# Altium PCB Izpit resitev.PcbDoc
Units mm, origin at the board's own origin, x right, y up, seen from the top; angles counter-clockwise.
Board outline 115 x 60 mm, 2 copper layers (Top Layer, Bottom Layer); 20 components, 19 nets, 110 pads, 8 vias.
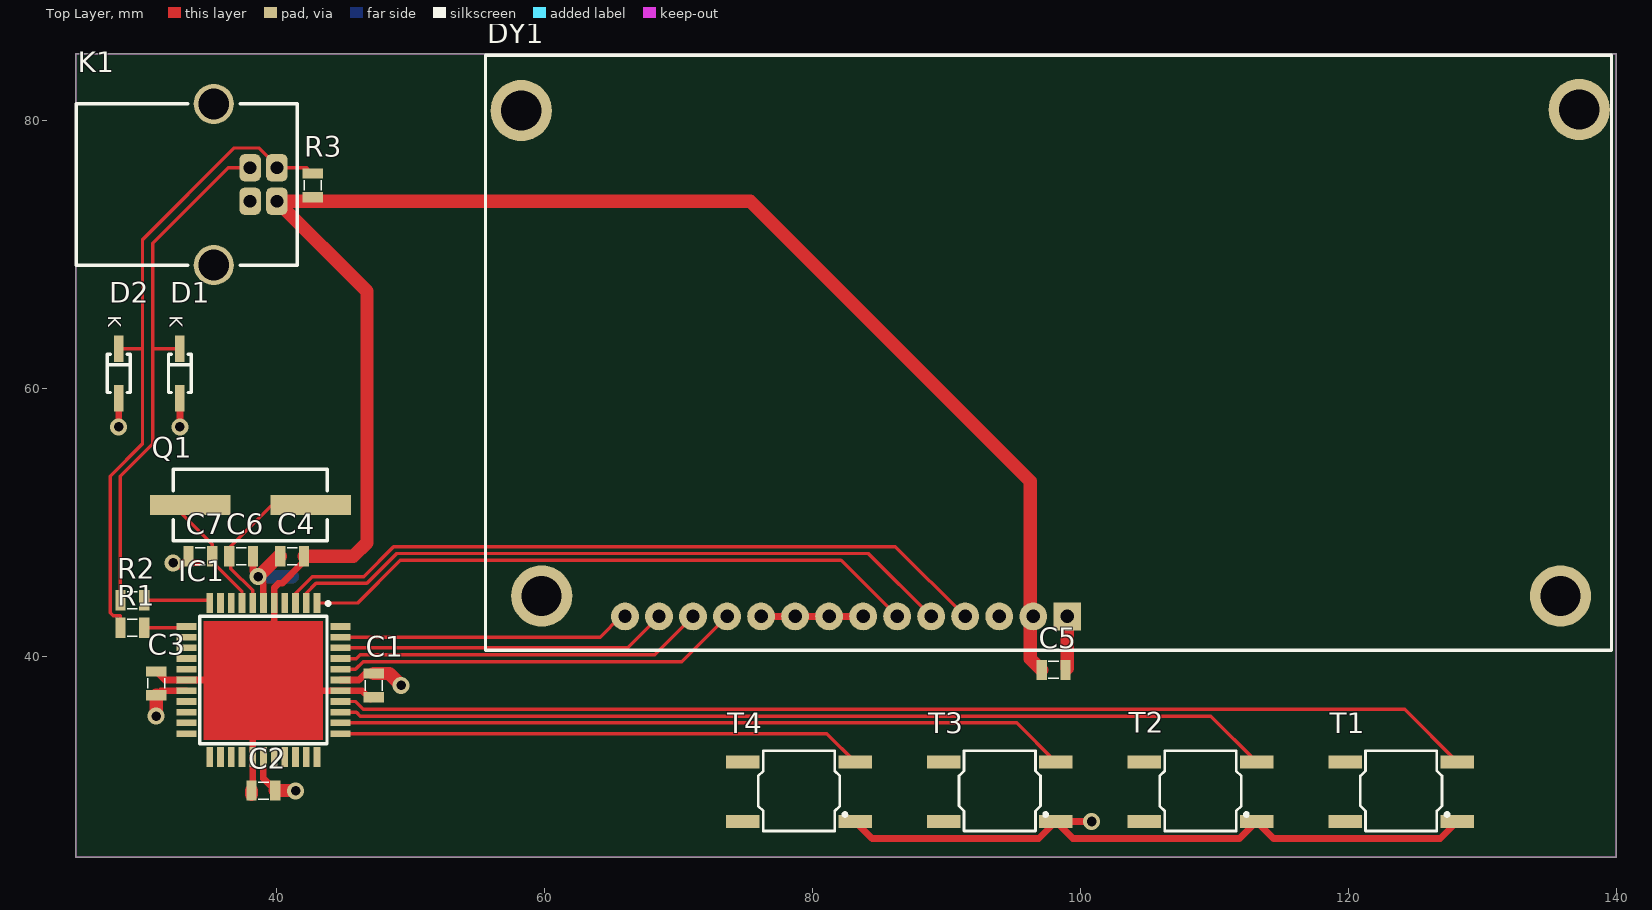
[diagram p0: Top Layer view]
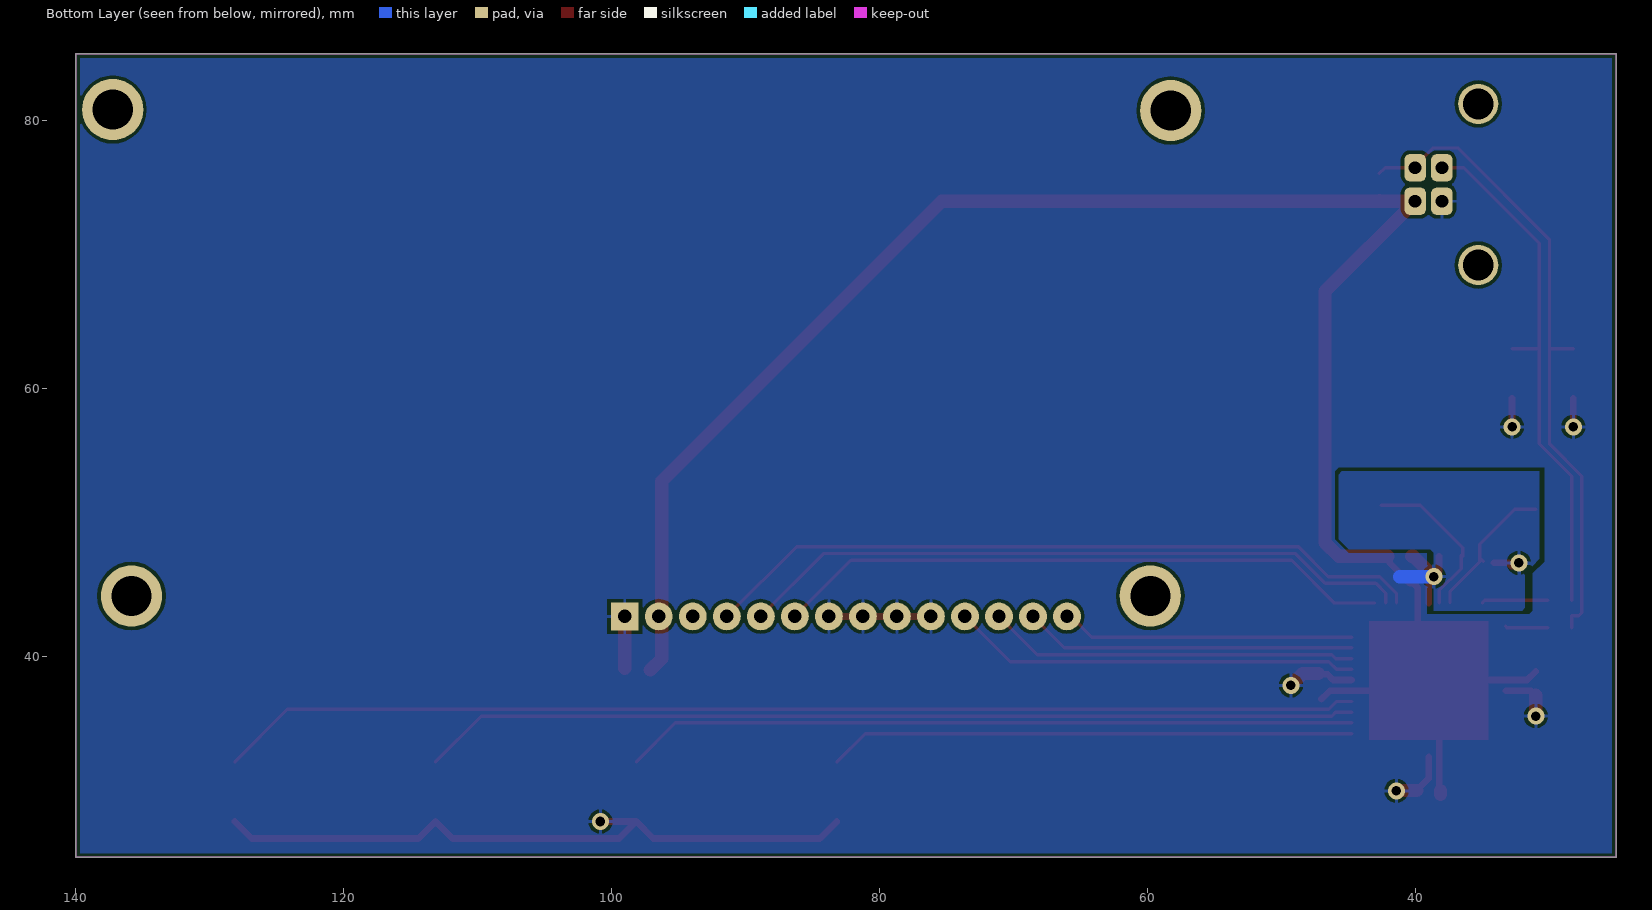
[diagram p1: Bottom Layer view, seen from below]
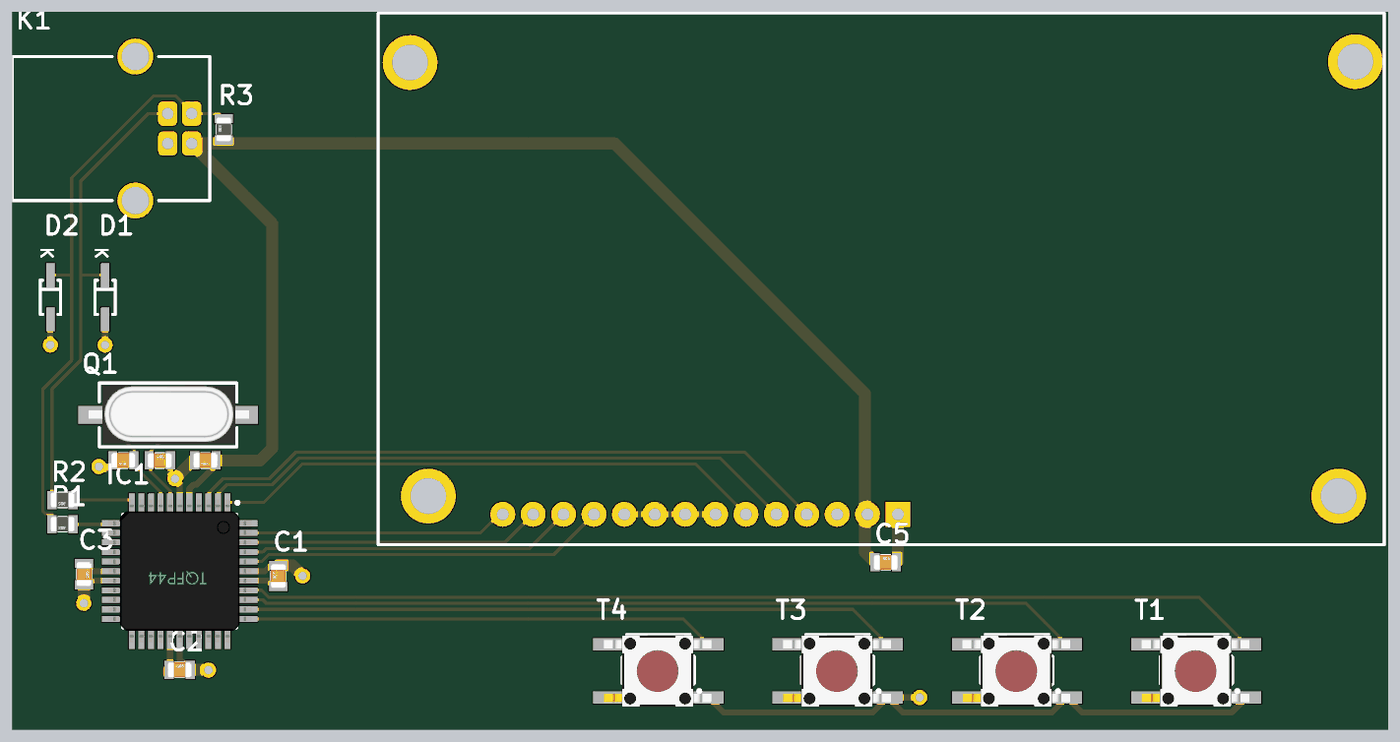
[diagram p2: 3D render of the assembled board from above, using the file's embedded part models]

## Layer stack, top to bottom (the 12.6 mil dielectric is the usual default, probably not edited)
Top Layer: signal copper 0.0356
Dielectric: dielectric 0.32, FR-4, Dk 4.8
Bottom Layer: signal copper 0.0356

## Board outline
25,25 25,85 140,85 140,25

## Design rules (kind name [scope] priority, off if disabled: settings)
Clearance [All] p1: gap=0.254
PolygonConnect [All] p1: connectstyle=Relief reliefconductorwidth=0.254 reliefentries=4 polygonreliefangle="90 Angle"
RoutingVias [All] p1: holewidth=0.711 width=1.27 viastyle="Through Hole" minholewidth=0.711 minwidth=1.27 maxholewidth=0.711 maxwidth=1.27
SilkscreenOverComponentPads [All] p1: minsilkscreentomaskgap=0.254
SolderMaskExpansion [All] p1: expansion=0.102
Width [All] p1: maxlimit=1 minlimit=0.254 preferedwidth=0.254
27 further rules are at their usual default settings.

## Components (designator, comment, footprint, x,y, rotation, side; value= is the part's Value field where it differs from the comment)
C1 "100n" C0805 47.244,37.846 r90 top
C2 "100n" C0805 39,30 r0 top
C3 "100n" C0805 31,38 r270 top
C4 "100n" C0805 41.148,47.498 r180 top
C5 "100n" C0805 98,39 r0 top
C6 "22p" C0805 37.338,47.498 r0 top
C7 "22p" C0805 34.29,47.498 r180 top
D1 "BZT52B3V6" SOD-123 32.766,62.992 r270 top
D2 "BZT52B3V6" SOD-123 28.194,62.992 r270 top
DY1 "LCD_HC16201" _LCD_LCD_HC16201(Primary) 66,43 r90 top
IC1 "ATMEGA324PA" TQFP44 43,44 r270 top
K1 "USB-B" _USB_B_90_F_USB-B-90F(Primary) 38,74 r90 top
Q1 "12MHz" Crystal_HC49 33.528,51.308 r0 top
R1 "68" R0805 29.21,42.164 r180 top
R2 "68" R0805 29.21,44.196 r180 top
R3 "1k5" R0805 42.672,75.184 r90 top
T1 "MINI 6X6" "SW 5x6 SMD SHORT" 123.952,29.972 r180 top
T2 "MINI 6X6" "SW 5x6 SMD SHORT" 108.966,29.972 r180 top
T3 "MINI 6X6" "SW 5x6 SMD SHORT" 93.98,29.972 r180 top
T4 "MINI 6X6" "SW 5x6 SMD SHORT" 78.994,29.972 r180 top

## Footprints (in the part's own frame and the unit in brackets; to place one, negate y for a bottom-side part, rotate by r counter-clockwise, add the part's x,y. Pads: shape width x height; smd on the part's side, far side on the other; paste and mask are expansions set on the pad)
_LCD_LCD_HC16201(Primary) [mil]
  round 180 hole 118: 15(1487,305) 16(1490,-2805) 17(60,-2750) 18(60,245)
  round 82 hole 39.37: Contrast(0,-1100) DB0(0,-700) DB1(0,-600) DB2(0,-500) DB3(0,-400) DB4(0,-300) DB5(0,-200) DB6(0,-100) DB7(0,0) E(0,-800) R/W(0,-900) RS(0,-1000) VDD(0,-1200)
  rect 82x82 hole 39.37: VSS(0,-1300)
  silkscreen extent -100,-2900 1650,410
_USB_B_90_F_USB-B-90F(Primary) [mm]
  rrect50% 2.032x1.6 hole 0.965: 1(0,-2.005) 2(2.5,-2.005) 3(2.5,-0.005) 4(0,-0.005)
  round 3 hole 2.3: 5(-4.77,2.705) 6(7.27,2.705)
  silkscreen extent -4.77,-3.51 7.27,12.99
C0805 [mil]
  rect 30x60 smd: 1(-35,0) 2(35,0)
  silkscreen extent -15,-25 15,25, body extent -39,-25 39,24, height 31
Crystal_HC49 [mm] "Crystall SMD short HC49"
  rect 6x1.5 smd: 1(0,0) 2(8.999,0)
  silkscreen extent -1.25,-2.67 10.25,2.67, body extent -2.13,-2.41 11.27,2.49, height 5.08
R0805 [mil]
  rect 30x60 smd: 1(-35,0) 2(35,0)
  silkscreen extent -15,-25 15,25, body extent -39,-25 39,24, height 31
SOD-123 [mm]
  rect 2x0.72 smd: 1(0,0) 2(3.701,0)
  silkscreen extent 0.43,-0.85 3.28,0.85
"SW 5x6 SMD SHORT" [mm]
  rect 2.5x1 smd: 1(-4.191,2.286) 2(-4.191,-2.159) 3(4.191,-2.159) 4(4.191,2.286)
  silkscreen extent -3.55,-3 3.05,3, body extent -4.45,-2.92 4.56,3.08, height 5
TQFP44 [mm]
  rect 1.5x0.5 smd: 1(0,0) 2(0,-0.8) 3(0,-1.6) 4(0,-2.4) 5(0,-3.2) 6(0,-4) 7(0,-4.801) 8(0,-5.601) 9(0,-6.401) 10(0,-7.201) 11(0,-8.001) 23(11.5,-8.001) 24(11.5,-7.201) 25(11.5,-6.401) 26(11.5,-5.601) 27(11.5,-4.801) 28(11.5,-4) 29(11.5,-3.2) 30(11.5,-2.4) 31(11.5,-1.6) 32(11.5,-0.8) 33(11.5,0)
  rect 0.5x1.5 smd: 12(1.749,-9.75) 13(2.549,-9.75) 14(3.35,-9.75) 15(4.15,-9.75) 16(4.95,-9.75) 17(5.75,-9.75) 18(6.55,-9.75) 19(7.35,-9.75) 20(8.15,-9.75) 21(8.95,-9.75) 22(9.75,-9.75) 34(9.75,1.749) 35(8.95,1.749) 36(8.15,1.749) 37(7.35,1.749) 38(6.55,1.749) 39(5.75,1.749) 40(4.95,1.749) 41(4.15,1.749) 42(3.35,1.749) 43(2.549,1.749) 44(1.749,1.749)
  silkscreen extent -0.09,-8.75 10.5,0.95, body extent -0.25,-9.99 11.75,2.01, height 1.02

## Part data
C1 C2 C3 C4 C5 C6 C7: library part C, "Capacitor"
D1 D2: library part BZT52B5V1, "BZT52B5V1"
Q1: library part Crystal, "Crystal"
R1 R2 R3: library part R, "R"

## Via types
v1: diameter 1.27, hole 0.711, Top Layer to Bottom Layer, 8 vias

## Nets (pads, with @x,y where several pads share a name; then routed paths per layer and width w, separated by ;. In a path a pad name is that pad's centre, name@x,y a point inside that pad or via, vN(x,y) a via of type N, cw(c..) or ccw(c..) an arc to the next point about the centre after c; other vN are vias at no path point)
D4: DY1.DB4 IC1.40 | length 30.5
  Top Layer w0.254: IC1.40 45.877,39.05 46.451,39.624 70.244,39.624 DY1.DB4
D5: DY1.DB5 IC1.41 | length 27.6
  Top Layer w0.254: IC1.41 45.946,39.85 46.228,40.132 68.212,40.132 DY1.DB5
D6: DY1.DB6 IC1.42 | length 24.8
  Top Layer w0.254: IC1.42 66.19,40.65 DY1.DB6
D7: DY1.DB7 IC1.43 | length 21.9
  Top Layer w0.254: IC1.43 64.144,41.451 65.693,43 DY1.DB7
E: DY1.E IC1.1 | length 46.4
  Top Layer w0.254: IC1.1 46.032,44 49.223,47.191 82.129,47.191 DY1.E
GND: C1.2 C2.2 C3.2 C4.2 C5.2 C6.2 C7.2 D1.2 D2.2 DY1.DB0 DY1.DB1 DY1.DB2 DY1.DB3 DY1.VSS IC1.6 IC1.18 IC1.28 IC1.39 K1.4 T1.1 T2.1 T3.1 T4.1 | length 90.5
  Top Layer w0.5: v1(28.194,57.15) D2.2 ; C3.2 31.339,37.45 IC1.18 ; v1@32.258,46.736 32.766,46.736 33.03,47 34.111,47 ; v1(32.766,57.15) D1.2 ; C6.2 38.227,46.355 v1(38.608,45.974) 39,45.582 IC1.6 ; IC1.28 39,30.89 C2.2 ; IC1.39 46.124,38.25 46.554,38.68 C1.2@46.791,38.68 ; DY1.DB3 DY1.DB2 DY1.DB1 DY1.DB0 83.78,42.966 DY1.DB0@83.82,42.926 ; T4.1 84.455,26.416 96.893,26.416 98.191,27.714 T3.1@98.219,27.686 ; C5.2 C5.2@99.02,39.131 ; v1(100.838,27.686) T3.1@98.219,27.686 ; T1.1 126.873,26.416 114.427,26.416 T2.1 111.887,26.416 99.441,26.416 T3.1 T3.1@98.219,27.686
  Top Layer w1: v1(30.988,35.56) 31,35.572 C3.2 ; v1(38.608,45.974) 40.132,47.498 C4.2 ; C2.2 41.374,30 v1(41.402,29.972) ; C1.2 48.387,38.735 v1(49.276,37.846) ; C5.2@99.02,39.131 DY1.VSS
  Bottom Layer w1: v1(38.608,45.974) 41.148,45.974
  other v1: 32.258,46.99
NetC6_1: C6.1 IC1.7 Q1.2 | length 12.3
  Top Layer w0.254: C6.1 36.449,48.133 39.624,51.308 Q1.2 ; C6.1@36.576,47.577 36.576,46.569 38.199,44.946 IC1.7
NetC7_1: C7.1 IC1.8 Q1.1 | length 10.9
  Top Layer w0.254: Q1.1@31,51 32.566,51 35.179,48.387 35.179,47.086 37.399,44.866 IC1.8 ; C7.1@34.925,47.117 C7.1@35.179,47.371
NetD1_1: D1.1 K1.3 R2.2 | length 39.3
  Top Layer w0.254: R2.2 28.321,53.467 30.734,55.88 30.734,62.992 ; D1.1 30.734,62.992 ; K1.3 36.368,76.5 30.734,70.866 30.734,62.992
NetD2_1: D2.1 K1.2 R1.2 R3.2 | length 48.8
  Top Layer w0.254: D2.1 29.972,62.992 ; R1.2 28.321,43.053 27.782,43.053 27.559,43.276 27.559,53.467 29.972,55.88 29.972,62.992 ; R3.2 42.245,76.5 K1.2 40.005,76.621 38.648,77.978 36.83,77.978 29.972,71.12 29.972,62.992
NetIC1_11: IC1.11 R2.1 | length 5
  Top Layer w0.254: R2.1 34.803,44.196 IC1.11
NetIC1_12: IC1.12 R1.1 | length 3.2
  Top Layer w0.254: R1.1 33.163,42.164 IC1.12
NetIC1_34: IC1.34 T4.2 | length 39.3
  Top Layer w0.254: IC1.34 81.066,34.25 T4.2
NetIC1_35: IC1.35 T3.2 | length 54.6
  Top Layer w0.254: IC1.35 95.252,35.05 T3.2
NetIC1_36: IC1.36 T2.2 | length 69.9
  Top Layer w0.254: IC1.36 45.951,35.85 46.241,35.56 109.728,35.56 T2.2
NetIC1_37: IC1.37 T1.2 | length 85.3
  Top Layer w0.254: IC1.37 45.869,36.65 46.451,36.068 124.206,36.068 T1.2
RS: DY1.RS IC1.3 | length 54.3
  Top Layer w0.254: IC1.3 41.4,44.739 42.635,45.974 46.482,45.974 48.715,48.207 86.193,48.207 DY1.RS
RW: DY1.R/W IC1.2 | length 50.6
  Top Layer w0.254: IC1.2 42.2,44.739 42.927,45.466 46.736,45.466 48.969,47.699 84.161,47.699 DY1.R/W
VCC: C1.1 C2.1 C3.1 C4.1 C5.1 DY1.VDD IC1.5 IC1.17 IC1.27 IC1.38 K1.1 R3.1 | length 151.2
  Top Layer w0.5: C3.1 31.639,38.25 IC1.17 35.456,38.25 39.8,42.594 ; C2.1 38.199,30.088 IC1.27 38.199,35.659 39.99,37.45 IC1.38 46.37,37.45 46.601,37.219 C1.1@46.99,36.83 ; 40.894,37.45 39.8,38.544 39.8,42.594 ; C4.1@41.889,47.35 41.889,46.969 40.386,45.466 40.132,45.466 39.8,45.134 IC1.5 39.8,42.594 ; R3.1@42.377,74 R3.1
  Top Layer w1: C2.1@38.111,29.718 C2.1 ; C4.1 45.72,47.498 46.736,48.514 46.736,67.269 K1.1 42.377,74 75.352,74 96.266,53.086 96.266,39.845 C5.1
pads on no net: DY1.15 DY1.16 DY1.17 DY1.18 DY1.Contrast IC1.4 IC1.9 IC1.10 IC1.13 IC1.14 IC1.15 IC1.16 IC1.19 IC1.20 IC1.21 IC1.22 IC1.23 IC1.24 IC1.25 IC1.26 IC1.29 IC1.30 IC1.31 IC1.32 IC1.33 IC1.44 K1.5 K1.6 T1.3 T1.4 T2.3 T2.4 T3.3 T3.4 T4.3 T4.4

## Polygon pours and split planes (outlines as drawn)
GND on Bottom Layer "še en" (solid, remove dead copper, pour order 11): 30.734,53.848 30.734,47.289 31.81,46.213 31.81,43.628 32.004,43.434 38.608,43.434 38.608,47.752 38.862,48.006 44.958,48.006 45.72,48.768 45.72,53.594 45.466,53.848
GND on Bottom Layer "še en" (solid, remove dead copper, pour order 4): 20.32,88.392 21.336,87.376 146.05,87.376 145.542,86.868 145.542,13.97 23.114,13.97 18.034,19.05

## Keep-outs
Keep-Out Layer:
  lines w0.102: 25,25 25,85 41,85 140,85 140,25 25,25

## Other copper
Top Layer:
  rectangle net VCC: 34.544,33.782 43.434,42.672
